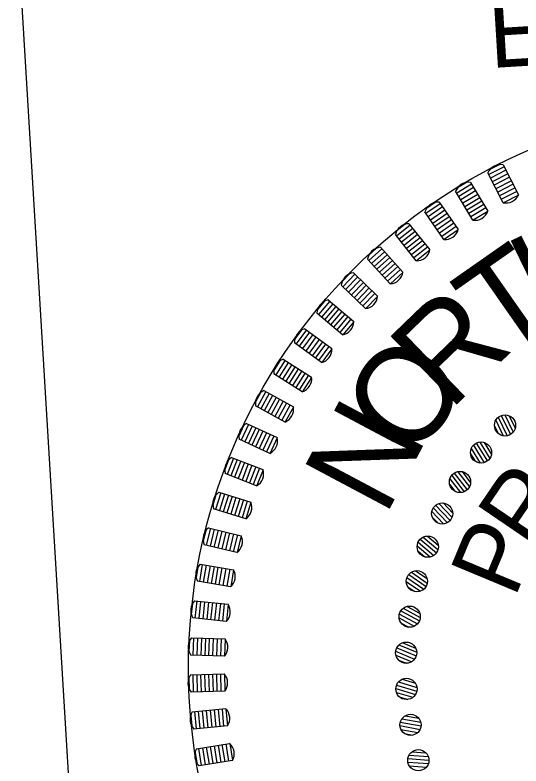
# Model space of a CAD drawing. Extents: x 2110128 to 2112690, y 669500 to 671339.
# Drawn here: x 2112240.6 to 2112277, y 670697.9 to 670751.9 of the extents above; entities that cross this region are included whole.
import ezdxf

# ---------------------------------------------------------------- set-up
doc = ezdxf.new("R2010")
doc.units = 0
doc.layers.add('Exist Roads Curbs Text', color=7, linetype='Continuous')
doc.layers.add('Exist Vegetation Woods Line Text', color=7, linetype='Continuous')

msp = doc.modelspace()

# ---------------------------------------------------------------- linework, layer by layer
at = {"layer": 'Exist Roads Curbs Text'}
msp.add_lwpolyline([(2112240.598, 670760.885), (2112340.465, 670766.938), (2112347.271, 670654.644), (2112247.404, 670648.591)], close=True, dxfattribs=at)
at = {"layer": 'Exist Vegetation Woods Line Text'}
for p, q in [((2112275.779, 670740.989), (2112274.667, 670740.419)), ((2112275.431, 670741.132), (2112274.754, 670740.784)), ((2112275.712, 670741.12), (2112276.815, 670738.97)), ((2112275.703, 670738.399), (2112274.6, 670740.55)), ((2112275.909, 670740.736), (2112274.797, 670740.165)), ((2112276.04, 670740.482), (2112274.927, 670739.911)), ((2112273.079, 670739.853), (2112272.426, 670739.462)), ((2112273.36, 670739.861), (2112274.603, 670737.788)), ((2112276.17, 670740.228), (2112275.058, 670739.657)), ((2112276.3, 670739.974), (2112275.188, 670739.403)), ((2112273.531, 670737.145), (2112272.288, 670739.218)), ((2112273.436, 670739.734), (2112272.364, 670739.091)), ((2112273.582, 670739.49), (2112272.51, 670738.847)), ((2112273.729, 670739.245), (2112272.657, 670738.602)), ((2112276.43, 670739.72), (2112275.318, 670739.15)), ((2112276.561, 670739.467), (2112275.448, 670738.896)), ((2112276.691, 670739.213), (2112275.579, 670738.642)), ((2112273.876, 670739), (2112272.804, 670738.357)), ((2112274.022, 670738.756), (2112272.95, 670738.113)), ((2112276.807, 670738.952), (2112275.723, 670738.395)), ((2112271.18, 670738.327), (2112270.153, 670737.615)), ((2112270.817, 670738.422), (2112270.191, 670737.988)), ((2112271.096, 670738.448), (2112272.474, 670736.462)), ((2112274.169, 670738.511), (2112273.097, 670737.868)), ((2112274.316, 670738.267), (2112273.244, 670737.624)), ((2112271.446, 670735.75), (2112270.069, 670737.736)), ((2112271.343, 670738.093), (2112270.316, 670737.38)), ((2112271.505, 670737.858), (2112270.478, 670737.146)), ((2112271.668, 670737.624), (2112270.641, 670736.912)), ((2112274.463, 670738.022), (2112273.391, 670737.379)), ((2112274.596, 670737.769), (2112273.551, 670737.142)), ((2112271.83, 670737.39), (2112270.803, 670736.677)), ((2112271.993, 670737.155), (2112270.966, 670736.443)), ((2112269.023, 670736.774), (2112268.045, 670735.995)), ((2112268.654, 670736.845), (2112268.058, 670736.371)), ((2112269.2, 670736.551), (2112268.222, 670735.772)), ((2112268.931, 670736.889), (2112270.437, 670734.999)), ((2112272.156, 670736.921), (2112271.128, 670736.208)), ((2112272.318, 670736.686), (2112271.291, 670735.974)), ((2112269.459, 670734.22), (2112267.953, 670736.11)), ((2112269.378, 670736.328), (2112268.4, 670735.549)), ((2112269.556, 670736.105), (2112268.578, 670735.326)), ((2112272.468, 670736.443), (2112271.466, 670735.748)), ((2112269.733, 670735.881), (2112268.756, 670735.103)), ((2112269.911, 670735.658), (2112268.933, 670734.88)), ((2112270.089, 670735.435), (2112269.111, 670734.656)), ((2112266.6, 670735.128), (2112266.037, 670734.615)), ((2112266.972, 670735.082), (2112266.048, 670734.24)), ((2112266.873, 670735.191), (2112268.501, 670733.404)), ((2112270.267, 670735.212), (2112269.289, 670734.433)), ((2112270.432, 670734.979), (2112269.479, 670734.22)), ((2112267.576, 670732.562), (2112265.949, 670734.349)), ((2112267.165, 670734.871), (2112266.24, 670734.029)), ((2112267.357, 670734.66), (2112266.432, 670733.818)), ((2112267.549, 670734.449), (2112266.624, 670733.607)), ((2112267.741, 670734.238), (2112266.817, 670733.396)), ((2112267.933, 670734.027), (2112267.009, 670733.185)), ((2112268.125, 670733.816), (2112267.201, 670732.975)), ((2112264.664, 670733.279), (2112264.136, 670732.73)), ((2112264.933, 670733.36), (2112266.674, 670731.684)), ((2112268.317, 670733.605), (2112267.393, 670732.764)), ((2112268.498, 670733.384), (2112267.596, 670732.563)), ((2112265.039, 670733.257), (2112264.172, 670732.357)), ((2112265.244, 670733.06), (2112264.378, 670732.159)), ((2112265.45, 670732.862), (2112264.583, 670731.961)), ((2112265.808, 670730.783), (2112264.066, 670732.459)), ((2112265.655, 670732.664), (2112264.789, 670731.763)), ((2112265.861, 670732.467), (2112264.994, 670731.566)), ((2112266.067, 670732.269), (2112265.2, 670731.368)), ((2112266.272, 670732.071), (2112265.406, 670731.17)), ((2112266.478, 670731.873), (2112265.611, 670730.972)), ((2112266.673, 670731.664), (2112265.828, 670730.786)), ((2112262.854, 670731.306), (2112262.364, 670730.724)), ((2112263.23, 670731.31), (2112262.425, 670730.353)), ((2112263.448, 670731.126), (2112262.643, 670730.17)), ((2112263.117, 670731.404), (2112264.966, 670729.848)), ((2112263.666, 670730.942), (2112262.861, 670729.986)), ((2112263.884, 670730.758), (2112263.079, 670729.802)), ((2112264.102, 670730.575), (2112263.297, 670729.618)), ((2112264.161, 670728.892), (2112262.312, 670730.448)), ((2112264.321, 670730.391), (2112263.516, 670729.435)), ((2112264.539, 670730.207), (2112263.734, 670729.251)), ((2112264.757, 670730.023), (2112263.952, 670729.067)), ((2112264.965, 670729.828), (2112264.18, 670728.895)), ((2112261.179, 670729.218), (2112260.728, 670728.605)), ((2112261.553, 670729.246), (2112260.813, 670728.239)), ((2112261.783, 670729.077), (2112261.043, 670728.07)), ((2112261.435, 670729.333), (2112263.382, 670727.902)), ((2112262.013, 670728.908), (2112261.273, 670727.901)), ((2112262.243, 670728.74), (2112261.503, 670727.732)), ((2112262.473, 670728.571), (2112261.733, 670727.563)), ((2112262.703, 670728.402), (2112261.963, 670727.394)), ((2112262.642, 670726.895), (2112260.694, 670728.326)), ((2112262.933, 670728.233), (2112262.192, 670727.225)), ((2112263.162, 670728.064), (2112262.422, 670727.057)), ((2112263.383, 670727.883), (2112262.661, 670726.9)), ((2112259.645, 670727.024), (2112259.236, 670726.382)), ((2112260.017, 670727.077), (2112259.345, 670726.023)), ((2112260.258, 670726.923), (2112259.586, 670725.869)), ((2112259.893, 670727.156), (2112261.931, 670725.857)), ((2112260.498, 670726.77), (2112259.826, 670725.716)), ((2112260.739, 670726.617), (2112260.067, 670725.563)), ((2112260.979, 670726.463), (2112260.307, 670725.409)), ((2112261.22, 670726.31), (2112260.548, 670725.256)), ((2112261.259, 670724.803), (2112259.221, 670726.102)), ((2112261.46, 670726.157), (2112260.788, 670725.103)), ((2112261.701, 670726.003), (2112261.029, 670724.949)), ((2112261.933, 670725.837), (2112261.278, 670724.809)), ((2112258.26, 670724.733), (2112257.894, 670724.066)), ((2112258.627, 670724.81), (2112258.027, 670723.714)), ((2112258.878, 670724.673), (2112258.277, 670723.577)), ((2112258.498, 670724.881), (2112260.618, 670723.72)), ((2112259.128, 670724.536), (2112258.527, 670723.44)), ((2112259.378, 670724.399), (2112258.777, 670723.303)), ((2112259.628, 670724.262), (2112259.027, 670723.166)), ((2112259.878, 670724.125), (2112259.277, 670723.029)), ((2112260.017, 670722.623), (2112257.897, 670723.785)), ((2112260.128, 670723.988), (2112259.527, 670722.892)), ((2112260.378, 670723.851), (2112259.778, 670722.754)), ((2112260.621, 670723.7), (2112260.035, 670722.631)), ((2112275.574, 670723.092), (2112276.228, 670721.721)), ((2112275.833, 670723.141), (2112276.428, 670721.891)), ((2112276.143, 670723.079), (2112276.576, 670722.172)), ((2112257.257, 670722.519), (2112259.449, 670721.5)), ((2112275.176, 670722.748), (2112275.709, 670721.629)), ((2112275.354, 670722.964), (2112275.989, 670721.631)), ((2112257.029, 670722.356), (2112256.708, 670721.665)), ((2112257.391, 670722.457), (2112256.864, 670721.324)), ((2112257.649, 670722.337), (2112257.122, 670721.203)), ((2112257.908, 670722.217), (2112257.381, 670721.083)), ((2112258.167, 670722.096), (2112257.64, 670720.963)), ((2112258.425, 670721.976), (2112257.898, 670720.843)), ((2112275.081, 670722.357), (2112275.345, 670721.801)), ((2112258.922, 670720.367), (2112256.73, 670721.386)), ((2112258.684, 670721.856), (2112258.157, 670720.722)), ((2112258.943, 670721.735), (2112258.416, 670720.602)), ((2112259.201, 670721.615), (2112258.674, 670720.482)), ((2112259.453, 670721.481), (2112258.939, 670720.375)), ((2112273.57, 670720.961), (2112274.341, 670719.701)), ((2112273.776, 670721.111), (2112274.569, 670719.816)), ((2112274.027, 670721.187), (2112274.75, 670720.006)), ((2112274.343, 670721.158), (2112274.868, 670720.3)), ((2112273.362, 670720.328), (2112273.683, 670719.803)), ((2112273.415, 670720.727), (2112274.063, 670719.67)), ((2112255.958, 670719.902), (2112255.683, 670719.192)), ((2112256.312, 670720.027), (2112255.861, 670718.861)), ((2112256.578, 670719.924), (2112256.127, 670718.759)), ((2112256.175, 670720.08), (2112258.429, 670719.209)), ((2112256.844, 670719.822), (2112256.393, 670718.656)), ((2112257.11, 670719.719), (2112256.659, 670718.553)), ((2112257.376, 670719.616), (2112256.925, 670718.45)), ((2112257.642, 670719.513), (2112257.191, 670718.347)), ((2112257.908, 670719.41), (2112257.457, 670718.244)), ((2112258.175, 670719.307), (2112257.724, 670718.141)), ((2112257.978, 670718.043), (2112255.724, 670718.915)), ((2112258.435, 670719.19), (2112257.995, 670718.053)), ((2112272.005, 670718.782), (2112272.904, 670717.61)), ((2112272.194, 670718.953), (2112273.118, 670717.748)), ((2112272.436, 670719.054), (2112273.279, 670717.956)), ((2112272.753, 670719.058), (2112273.365, 670718.261)), ((2112271.876, 670718.533), (2112272.63, 670717.549)), ((2112271.864, 670718.131), (2112272.238, 670717.642)), ((2112255.052, 670717.383), (2112254.824, 670716.657)), ((2112255.397, 670717.532), (2112255.024, 670716.338)), ((2112255.256, 670717.576), (2112257.563, 670716.854)), ((2112255.669, 670717.446), (2112255.296, 670716.253)), ((2112255.941, 670717.361), (2112255.568, 670716.168)), ((2112256.213, 670717.276), (2112255.84, 670716.083)), ((2112256.486, 670717.191), (2112256.113, 670715.998)), ((2112256.758, 670717.106), (2112256.385, 670715.913)), ((2112257.03, 670717.021), (2112256.657, 670715.828)), ((2112257.303, 670716.936), (2112256.93, 670715.743)), ((2112257.57, 670716.836), (2112257.206, 670715.672)), ((2112270.846, 670716.641), (2112271.892, 670715.539)), ((2112271.077, 670716.767), (2112272.03, 670715.763)), ((2112271.392, 670716.805), (2112272.084, 670716.075)), ((2112257.19, 670715.661), (2112254.883, 670716.382)), ((2112270.574, 670716.19), (2112271.427, 670715.291)), ((2112270.677, 670716.451), (2112271.693, 670715.38)), ((2112270.604, 670715.789), (2112271.028, 670715.343)), ((2112254.648, 670714.981), (2112254.355, 670713.766)), ((2112254.505, 670715.015), (2112256.854, 670714.448)), ((2112254.925, 670714.914), (2112254.632, 670713.699)), ((2112254.313, 670714.81), (2112254.135, 670714.07)), ((2112255.203, 670714.847), (2112254.909, 670713.632)), ((2112255.48, 670714.78), (2112255.187, 670713.565)), ((2112255.757, 670714.713), (2112255.464, 670713.498)), ((2112256.035, 670714.646), (2112255.741, 670713.431)), ((2112256.312, 670714.579), (2112256.019, 670713.364)), ((2112256.589, 670714.512), (2112256.296, 670713.297)), ((2112256.863, 670714.43), (2112256.577, 670713.245)), ((2112270.273, 670714.421), (2112271.038, 670713.768)), ((2112269.599, 670713.994), (2112270.722, 670713.035)), ((2112269.748, 670714.201), (2112270.903, 670713.214)), ((2112269.964, 670714.351), (2112271.017, 670713.451)), ((2112256.561, 670713.233), (2112254.212, 670713.8)), ((2112269.524, 670713.724), (2112270.467, 670712.919)), ((2112269.596, 670713.328), (2112270.064, 670712.929)), ((2112254.07, 670712.386), (2112253.857, 670711.154)), ((2112253.925, 670712.411), (2112256.306, 670712)), ((2112254.351, 670712.338), (2112254.138, 670711.106)), ((2112254.632, 670712.289), (2112254.42, 670711.057)), ((2112254.913, 670712.241), (2112254.701, 670711.009)), ((2112253.747, 670712.194), (2112253.618, 670711.443)), ((2112255.194, 670712.192), (2112254.982, 670710.96)), ((2112255.475, 670712.144), (2112255.263, 670710.912)), ((2112255.756, 670712.095), (2112255.544, 670710.863)), ((2112256.037, 670712.047), (2112255.825, 670710.815)), ((2112256.316, 670711.983), (2112256.109, 670710.782)), ((2112268.911, 670711.66), (2112270.162, 670710.799)), ((2112269.11, 670711.831), (2112270.251, 670711.046)), ((2112269.41, 670711.933), (2112270.238, 670711.363)), ((2112256.094, 670710.769), (2112253.712, 670711.179)), ((2112268.738, 670711.162), (2112269.759, 670710.459)), ((2112268.784, 670711.438), (2112270.001, 670710.602)), ((2112268.851, 670710.776), (2112269.358, 670710.427)), ((2112253.355, 670709.546), (2112253.275, 670708.788)), ((2112253.518, 670709.774), (2112255.921, 670709.522)), ((2112253.664, 670709.759), (2112253.534, 670708.515)), ((2112253.948, 670709.729), (2112253.817, 670708.486)), ((2112254.231, 670709.699), (2112254.101, 670708.456)), ((2112254.515, 670709.669), (2112254.385, 670708.426)), ((2112254.799, 670709.64), (2112254.668, 670708.396)), ((2112255.083, 670709.61), (2112254.952, 670708.367)), ((2112255.366, 670709.58), (2112255.236, 670708.337)), ((2112255.65, 670709.55), (2112255.519, 670708.307)), ((2112255.932, 670709.505), (2112255.805, 670708.293)), ((2112268.344, 670709.045), (2112269.678, 670708.32)), ((2112268.524, 670709.236), (2112269.74, 670708.575)), ((2112268.812, 670709.369), (2112269.695, 670708.889)), ((2112255.791, 670708.279), (2112253.387, 670708.531)), ((2112268.223, 670708.532), (2112269.313, 670707.94)), ((2112268.241, 670708.811), (2112269.538, 670708.106)), ((2112268.377, 670708.159), (2112268.917, 670707.866)), ((2112253.139, 670706.877), (2112253.109, 670706.116)), ((2112253.286, 670707.116), (2112255.701, 670707.023)), ((2112253.433, 670707.11), (2112253.385, 670705.861)), ((2112253.718, 670707.099), (2112253.67, 670705.85)), ((2112254.003, 670707.088), (2112253.955, 670705.839)), ((2112254.288, 670707.078), (2112254.24, 670705.828)), ((2112254.573, 670707.067), (2112254.525, 670705.817)), ((2112254.858, 670707.056), (2112254.81, 670705.806)), ((2112255.143, 670707.045), (2112255.095, 670705.795)), ((2112255.428, 670707.034), (2112255.38, 670705.785)), ((2112255.713, 670707.007), (2112255.666, 670705.789)), ((2112268.053, 670706.385), (2112269.456, 670705.803)), ((2112268.212, 670706.594), (2112269.491, 670706.063)), ((2112268.485, 670706.756), (2112269.413, 670706.371)), ((2112255.653, 670705.774), (2112253.238, 670705.867)), ((2112267.975, 670706.142), (2112269.339, 670705.576)), ((2112267.987, 670705.862), (2112269.133, 670705.387)), ((2112268.178, 670705.508), (2112268.747, 670705.272)), ((2112253.099, 670704.2), (2112253.12, 670703.439)), ((2112253.23, 670704.448), (2112255.646, 670704.515)), ((2112253.377, 670704.453), (2112253.412, 670703.203)), ((2112253.663, 670704.46), (2112253.697, 670703.211)), ((2112253.948, 670704.468), (2112253.982, 670703.219)), ((2112254.233, 670704.476), (2112254.267, 670703.227)), ((2112254.518, 670704.484), (2112254.553, 670703.235)), ((2112254.803, 670704.492), (2112254.838, 670703.242)), ((2112255.088, 670704.5), (2112255.123, 670703.25)), ((2112255.373, 670704.508), (2112255.408, 670703.258)), ((2112255.659, 670704.5), (2112255.693, 670703.282)), ((2112268.432, 670704.123), (2112269.396, 670703.837)), ((2112268.042, 670703.709), (2112269.498, 670703.277)), ((2112268.178, 670703.933), (2112269.506, 670703.54)), ((2112255.681, 670703.266), (2112253.265, 670703.199)), ((2112267.99, 670703.459), (2112269.406, 670703.039)), ((2112268.031, 670703.182), (2112269.22, 670702.83)), ((2112268.258, 670702.85), (2112268.848, 670702.675)), ((2112253.351, 670701.783), (2112255.757, 670702.01)), ((2112255.202, 670701.957), (2112255.319, 670700.713)), ((2112255.486, 670701.984), (2112255.603, 670700.739)), ((2112255.771, 670701.995), (2112255.885, 670700.782)), ((2112253.236, 670701.527), (2112253.308, 670700.769)), ((2112253.498, 670701.797), (2112253.615, 670700.552)), ((2112253.782, 670701.824), (2112253.899, 670700.579)), ((2112254.066, 670701.85), (2112254.183, 670700.606)), ((2112254.35, 670701.877), (2112254.467, 670700.632)), ((2112254.634, 670701.904), (2112254.751, 670700.659)), ((2112254.918, 670701.931), (2112255.035, 670700.686)), ((2112268.656, 670701.499), (2112269.644, 670701.316)), ((2112268.311, 670701.047), (2112269.804, 670700.769)), ((2112268.423, 670701.284), (2112269.784, 670701.031)), ((2112255.874, 670700.765), (2112253.468, 670700.538)), ((2112268.285, 670700.793), (2112269.737, 670700.523)), ((2112268.355, 670700.522), (2112269.574, 670700.295)), ((2112268.616, 670700.215), (2112269.221, 670700.102)), ((2112253.648, 670699.131), (2112256.034, 670699.516)), ((2112254.356, 670699.246), (2112254.555, 670698.012)), ((2112254.638, 670699.291), (2112254.837, 670698.057)), ((2112254.919, 670699.337), (2112255.119, 670698.103)), ((2112255.201, 670699.382), (2112255.4, 670698.148)), ((2112255.483, 670699.428), (2112255.682, 670698.193)), ((2112255.764, 670699.473), (2112255.963, 670698.239)), ((2112256.048, 670699.503), (2112256.243, 670698.3)), ((2112253.55, 670698.868), (2112253.672, 670698.117)), ((2112253.793, 670699.155), (2112253.992, 670697.921)), ((2112254.075, 670699.2), (2112254.274, 670697.966)), ((2112269.152, 670698.913), (2112270.154, 670698.834)), ((2112256.233, 670698.282), (2112253.847, 670697.897)), ((2112268.856, 670698.427), (2112270.37, 670698.307)), ((2112268.857, 670698.172), (2112270.329, 670698.056)), ((2112268.943, 670698.675), (2112270.323, 670698.566)), ((2112268.955, 670697.909), (2112270.191, 670697.812))]:
    msp.add_line(p, q, dxfattribs=at)
for centre, radius in [((2112293.63, 670704.945), 40.556), ((2112275.843, 670722.379), 0.762), ((2112274.117, 670720.43), 0.762), ((2112272.605, 670718.311), 0.762), ((2112271.322, 670716.046), 0.762), ((2112270.283, 670713.659), 0.762), ((2112269.5, 670711.176), 0.762), ((2112268.98, 670708.625), 0.762), ((2112268.73, 670706.034), 0.762), ((2112268.751, 670703.431), 0.762), ((2112269.045, 670700.844), 0.762), ((2112269.608, 670698.302), 0.762)]:
    msp.add_circle(centre, radius, dxfattribs=at)
for centre, radius, start, end in [((2112275.531, 670740.104), 1.032, 79.8963, 154.4372), ((2112273.246, 670738.835), 1.032, 83.6857, 158.2267), ((2112275.913, 670739.36), 0.983, 257.67, 336.6635), ((2112271.051, 670737.417), 1.032, 87.4752, 162.0162), ((2112273.677, 670738.117), 0.983, 261.4595, 340.453), ((2112268.954, 670735.857), 1.032, 91.2647, 165.8056), ((2112271.528, 670736.729), 0.983, 265.2489, 344.2424), ((2112266.964, 670734.162), 1.032, 95.0542, 169.5951), ((2112269.475, 670735.203), 0.983, 269.0384, 348.0319), ((2112265.091, 670732.34), 1.032, 98.8436, 173.3846), ((2112267.528, 670733.544), 0.983, 272.8279, 351.8214), ((2112265.695, 670731.759), 0.983, 276.6174, 355.6109), ((2112263.343, 670730.397), 1.032, 102.6331, 177.1741), ((2112263.983, 670729.858), 0.983, 280.4068, 359.4003), ((2112261.726, 670728.343), 1.032, 106.4226, 180.9635), ((2112262.401, 670727.848), 0.983, 284.1963, 3.1898), ((2112260.249, 670726.187), 1.032, 110.212, 184.753), ((2112260.955, 670725.737), 0.983, 287.9858, 6.9793), ((2112258.918, 670723.938), 1.032, 114.0015, 188.5425), ((2112259.652, 670723.536), 0.983, 291.7753, 10.7688), ((2112257.738, 670721.606), 1.032, 117.791, 192.332), ((2112258.497, 670721.253), 0.983, 295.5647, 14.5582), ((2112256.715, 670719.201), 1.032, 121.5805, 196.1214), ((2112257.496, 670718.899), 0.983, 299.3542, 18.3477), ((2112255.854, 670716.734), 1.032, 125.3699, 199.9109), ((2112256.653, 670716.484), 0.983, 303.1437, 22.1372), ((2112255.157, 670714.215), 1.032, 129.1594, 203.7004), ((2112255.97, 670714.019), 0.983, 306.9332, 25.9266), ((2112254.628, 670711.656), 1.032, 132.9489, 207.4899), ((2112255.453, 670711.513), 0.983, 310.7226, 29.7161), ((2112254.269, 670709.067), 1.032, 136.7384, 211.2793), ((2112255.102, 670708.979), 0.983, 314.5121, 33.5056), ((2112254.083, 670706.46), 1.032, 140.5278, 215.0688), ((2112254.919, 670706.428), 0.983, 318.3016, 37.2951), ((2112254.069, 670703.846), 1.032, 144.3173, 218.8583), ((2112254.905, 670703.87), 0.983, 322.091, 41.0845), ((2112255.061, 670701.316), 0.983, 325.8805, 44.874), ((2112254.227, 670701.238), 1.032, 148.1068, 222.6478), ((2112255.385, 670698.779), 0.983, 329.67, 48.6635), ((2112254.558, 670698.645), 1.032, 151.8963, 226.4372)]:
    msp.add_arc(centre, radius, start, end, dxfattribs=at)

# ---------------------------------------------------------------- texts
at = {"layer": 'Exist Roads Curbs Text'}
msp.add_text('ENGINEER', height=5.0001, rotation=3.4682, dxfattribs=at).set_placement((2112274.786, 670748.08))
at = {"layer": 'Exist Vegetation Woods Line Text'}
for s, height, rotation, p in [('H', 6.846, 25.9825, (2112278.575, 670729.174)), ('T', 6.846, 34.9825, (2112275.61, 670726.977)), ('R', 6.846, 43.9825, (2112271.821, 670723.352)), ('O', 6.846, 52.9825, (2112269.209, 670719.722)), ('N', 6.846, 61.9825, (2112267.197, 670715.728)), ('R', 5.135, 55.7406, (2112277.86, 670713.205)), ('P', 5.135, 67.3535, (2112276.519, 670709.873))]:
    msp.add_text(s, height=height, rotation=rotation, dxfattribs=at).set_placement(p)

doc.saveas('drawing.dxf')
